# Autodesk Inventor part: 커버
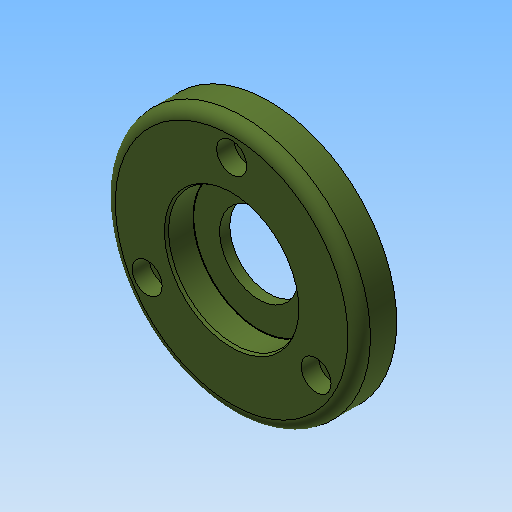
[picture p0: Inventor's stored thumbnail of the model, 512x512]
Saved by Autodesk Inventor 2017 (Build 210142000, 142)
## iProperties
Created: 2016-06
Part Number: 커버
Material: 알루미늄 6061
Document SubType Name: Modeling
Designer: mduedu
Density: 2.71 g/cm^3
Appearance: 올리브 녹색
Author: mduedu
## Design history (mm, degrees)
sketch "스케치1"
  geometry: C1 r 34 at (0, 0); 1 further point
  constraints: 1 centre point, 1 coincident
  dimensions: "d0" = 68 diameter of C1
extrude "돌출1" new body sketch "스케치1" distance "d2" = 10; taper "d3" = 0 deg
sketch "스케치2"
  geometry: C1 r 21 at (0, 0); 1 further point
  constraints: 1 centre point, 1 coincident
  dimensions: "d4" = 42 diameter of C1
extrude "돌출2" join sketch "스케치2" distance "d6" = 3; taper "d7" = 0 deg
fillet "모깎기1" dims "d8" = 3
hole "구멍1" diameter "d11" = 35; stored, may be unused: countersink angle "d15" = 90 deg, drill point angle "d17" = 0 deg; dims "d9" = 10, "d10" = 10, "d12" = 6, "d13" = 4, "d14" = 2, "d16" = 3
hole "구멍2" diameter "d20" = 35; stored, may be unused: countersink angle "d24" = 90 deg, drill point angle "d26" = 0 deg; dims "d21" = 6, "d22" = 4, "d23" = 2, "d25" = 7.3, "d73" = 10, "d74" = 10
hole "구멍3" diameter "d29" = 21; stored, may be unused: countersink angle "d33" = 90 deg, drill point angle "d35" = 0 deg; dims "d27" = 10, "d28" = 10, "d30" = 6, "d31" = 4, "d32" = 2, "d34" = 5
fillet "모깎기2" dims "d36" = 3
fillet "모깎기3" dims "d37" = 0.1
chamfer "모따기1" distance "d38" = 0.7; stored, may be unused: second distance "d39" = 2, angle "d40" = 30 deg
chamfer "모따기2" distance "d42" = 0.5; stored, may be unused: second distance "d43" = 2, angle "d44" = 30 deg
sketch "스케치5" dims "d60" = 52
  geometry: 3 further points
  constraints: 2 vertical alignment, 1 coincident, 2 other
hole "구멍5" sketch "스케치5" at (0, 26) diameter "d61" = 4.5; stored, may be unused: countersink angle "d65" = 90 deg, drill point angle "d67" = 118 deg; dims "d62" = 6, "d63" = 8, "d64" = 4.6, "d66" = 8
node "솔리드1"
pattern_circular "원형 패턴1" dims angle "d69" = 360 deg
